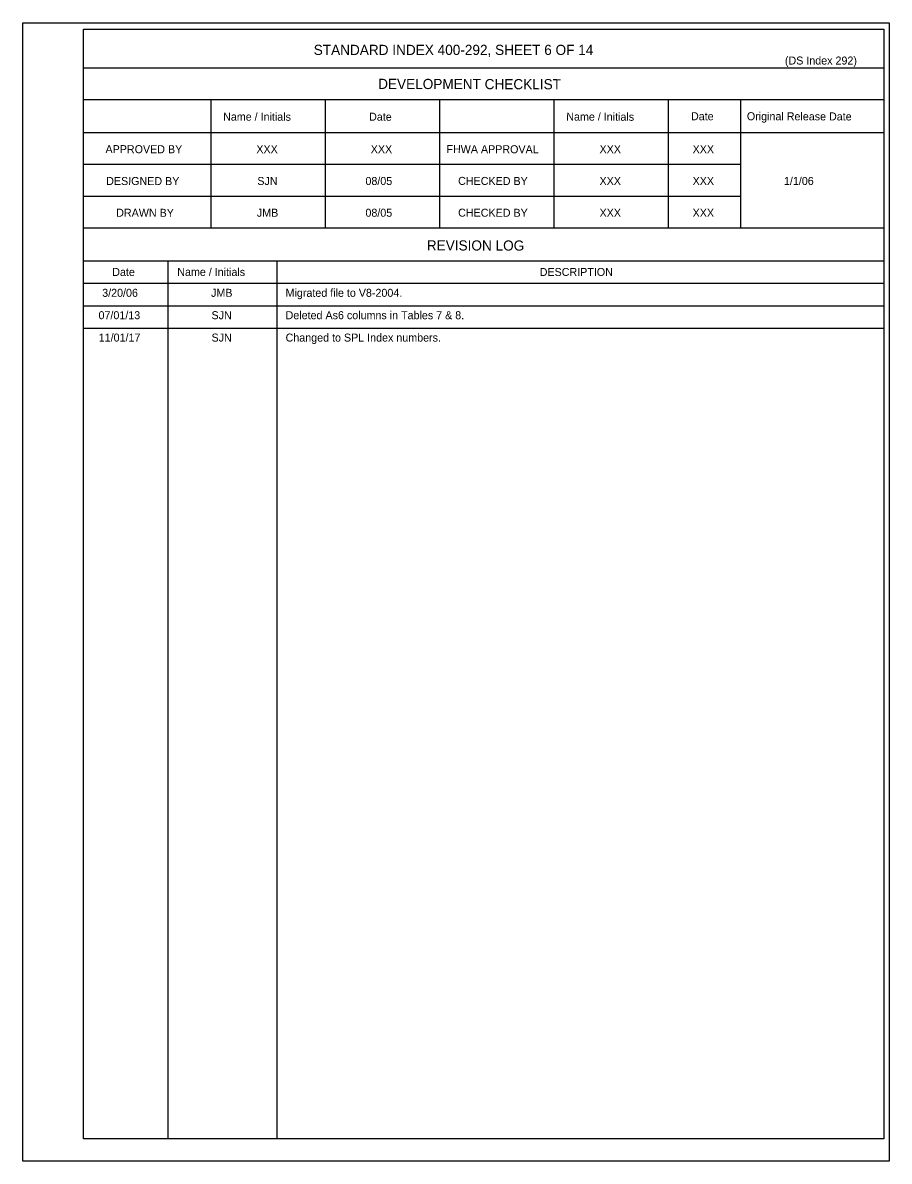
# Model space of a CAD drawing. Extents: x 10351.18 to 10353.4, y 76399.49 to 76400.59.
# Drawn here: x 10352.716 to 10353.397, y 76399.632 to 76400.528 of the extents above; entities that cross this region are included whole.
import ezdxf

# ---------------------------------------------------------------- set-up
doc = ezdxf.new("R2010")
doc.units = 0
doc.layers.add('AdhocPoint_dp', color=7, linetype='Continuous')
doc.layers.add('Border', color=7, linetype='Continuous')

msp = doc.modelspace()

# ---------------------------------------------------------------- linework, layer by layer
at = {"layer": 'AdhocPoint_dp'}
for p, q in [((10352.76364, 76400.30505), (10353.39322, 76400.30505)), ((10352.76364, 76400.28743), (10353.39322, 76400.28743))]:
    msp.add_line(p, q, dxfattribs=at)
at = {"layer": 'Border'}
for p, q in [((10353.39322, 76400.49202), (10352.76364, 76400.49202)), ((10353.39322, 76400.46702), (10352.76364, 76400.46702)), ((10352.86364, 76400.46702), (10352.86364, 76400.36615)), ((10352.95364, 76400.46702), (10352.95364, 76400.36615)), ((10353.04364, 76400.46702), (10353.04364, 76400.36615)), ((10353.13363, 76400.46702), (10353.13363, 76400.36615)), ((10353.22363, 76400.46702), (10353.22363, 76400.36615)), ((10353.28035, 76400.46702), (10353.28035, 76400.36615)), ((10353.39322, 76400.44115), (10352.76364, 76400.44115)), ((10353.28035, 76400.41615), (10352.76364, 76400.41615)), ((10353.28035, 76400.39115), (10352.76364, 76400.39115)), ((10353.39322, 76400.36615), (10352.76364, 76400.36615)), ((10353.39322, 76400.34028), (10352.76364, 76400.34028)), ((10352.8299, 76400.34028), (10352.8299, 76399.64945)), ((10352.91559, 76400.34028), (10352.91559, 76399.64945)), ((10353.39322, 76400.32266), (10352.76364, 76400.32266)), ((10352.71581, 76399.63191), (10352.71581, 76399.63191))]:
    msp.add_line(p, q, dxfattribs=at)
for points in [[(10352.71581, 76400.52774), (10353.39748, 76400.52774), (10353.39748, 76399.63191), (10352.71581, 76399.63191)], [(10352.76364, 76400.52266), (10353.39322, 76400.52266), (10353.39322, 76399.64945), (10352.76364, 76399.64945)]]:
    msp.add_lwpolyline(points, close=True, dxfattribs=at)

# ---------------------------------------------------------------- texts
at = {"layer": 'AdhocPoint_dp'}
for s, height, p in [('STANDARD INDEX 400-292, SHEET 6 OF 14', 0.008, (10352.94471, 76400.50241)), ('(DS Index 292)', 0.0063, (10353.31541, 76400.49487)), ('XXX', 0.0063, (10352.89957, 76400.42511)), ('XXX', 0.0063, (10352.98957, 76400.42511)), ('XXX', 0.0063, (10353.16957, 76400.42511)), ('XXX', 0.0063, (10353.2428, 76400.42511)), ('SJN', 0.0063, (10352.90034, 76400.40011)), ('08/05', 0.0063, (10352.98539, 76400.40011)), ('XXX', 0.0063, (10353.16957, 76400.40011)), ('XXX', 0.0063, (10353.2428, 76400.40011)), ('1/1/06', 0.0063, (10353.31465, 76400.40011)), ('JMB', 0.0063, (10352.89998, 76400.37511)), ('08/05', 0.0063, (10352.98539, 76400.37511)), ('XXX', 0.0063, (10353.16957, 76400.37511)), ('XXX', 0.0063, (10353.2428, 76400.37511)), ('DESCRIPTION', 0.0063, (10353.1225, 76400.3285)), ('3/20/06', 0.0063, (10352.7783, 76400.3121)), ('JMB', 0.0063, (10352.86394, 76400.3121)), ('Migrated file to V8-2004.', 0.0063, (10352.92258, 76400.3121)), ('07/01/13', 0.0063, (10352.7754, 76400.29448)), ('SJN', 0.0063, (10352.8643, 76400.29448)), ('Deleted As6 columns in Tables 7 & 8.', 0.0063, (10352.92258, 76400.29448)), ('11/01/17', 0.0063, (10352.77555, 76400.27687)), ('SJN', 0.0063, (10352.8643, 76400.27687)), ('Changed to SPL Index numbers.', 0.0063, (10352.92258, 76400.27687))]:
    msp.add_text(s, height=height, dxfattribs=at).set_placement(p)
for s, height, p in [('DEVELOPMENT CHECKLIST', 0.008, (10352.99538, 76400.47567)), ('Name / Initials', 0.0063, (10352.87341, 76400.45074)), ('Date', 0.0063, (10352.98824, 76400.45069)), ('Name / Initials', 0.0063, (10353.1434, 76400.45074)), ('Date', 0.0063, (10353.24152, 76400.45105)), ('Original Release Date', 0.0063, (10353.28547, 76400.45105)), ('APPROVED BY', 0.0063, (10352.78088, 76400.42517)), ('FHWA APPROVAL', 0.0063, (10353.04911, 76400.42517)), ('DESIGNED BY', 0.0063, (10352.78141, 76400.40012)), ('CHECKED BY', 0.0063, (10353.05832, 76400.40017)), ('DRAWN BY', 0.0063, (10352.78931, 76400.37512)), ('CHECKED BY', 0.0063, (10353.05832, 76400.37517)), ('REVISION LOG', 0.008, (10353.03367, 76400.34861)), ('Date', 0.0063, (10352.78621, 76400.32852)), ('Name / Initials', 0.0063, (10352.83735, 76400.32857))]:
    msp.add_text(s, height=height, rotation=359.87563, dxfattribs=at).set_placement(p)

doc.saveas('drawing.dxf')
